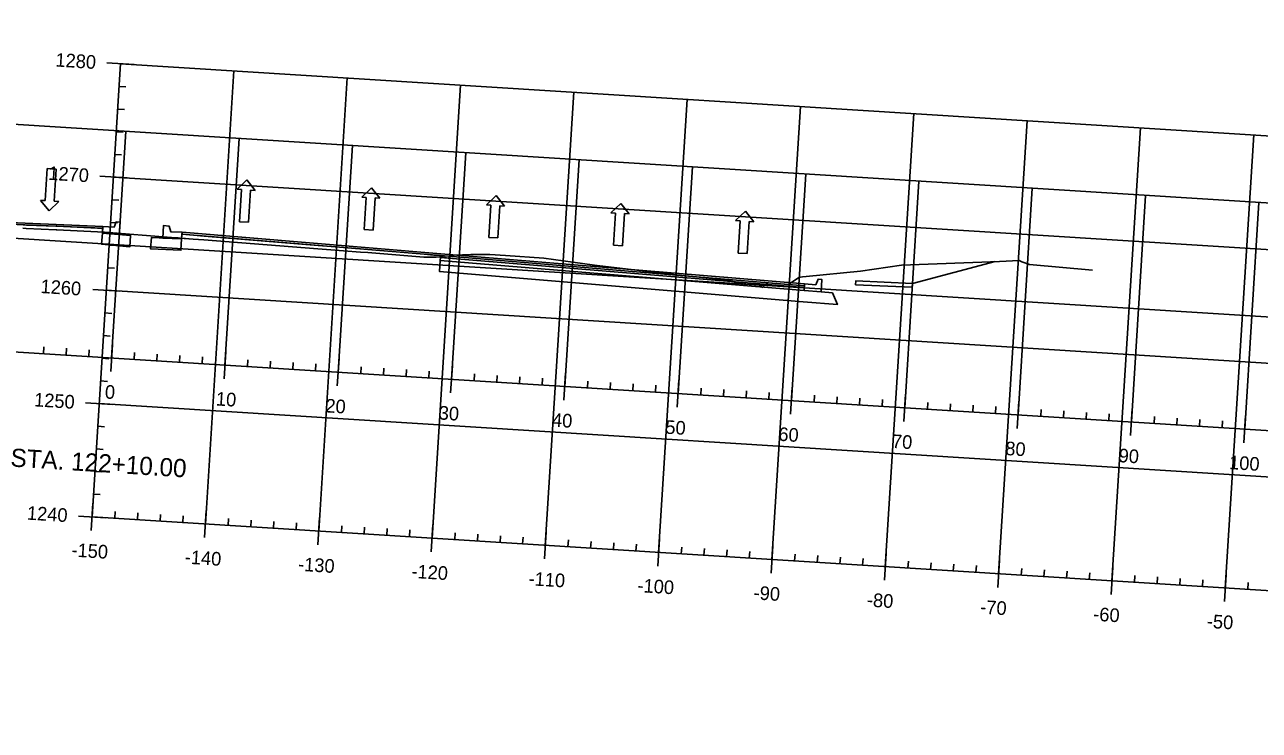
# Model space of a CAD drawing. Extents: x 658976 to 668721, y 639543 to 647196.
# Drawn here: x 660372 to 660916, y 641901 to 642211 of the extents above; entities that cross this region are included whole.
import ezdxf

# ---------------------------------------------------------------- set-up
doc = ezdxf.new("R2010")
doc.units = 0
for name, color, linetype in [('R_Axis', 7, 'Continuous'), ('R_Axis Annot', 7, 'Continuous'), ('R_Exist Surface', 7, 'Continuous'), ('R_Fin Surface', 7, 'Continuous'), ('R_Grid', 7, 'Continuous'), ('R_MOT', 7, 'Continuous'), ('R_Proposed Const Limits', 7, 'Continuous'), ('R_Proposed Road', 7, 'Continuous'), ('R_Sub Surface', 7, 'Continuous')]:
    doc.layers.add(name, color=color, linetype=linetype)

msp = doc.modelspace()

# ---------------------------------------------------------------- linework, layer by layer
for points in [[(660406.87, 642122.59), (660411.85, 642122.18), (660412.84, 642124.62), (660414.5, 642124.52), (660414.16, 642119.06), (660406.69, 642119.68)], [(660441.77, 642120), (660436.78, 642120.21), (660436.1, 642122.76), (660433.61, 642122.92), (660433.26, 642117.44), (660441.59, 642117.09)], [(660715.89, 642097.27), (660720.87, 642096.86), (660721.86, 642099.3), (660723.52, 642099.2), (660723.18, 642093.74), (660715.71, 642094.36)]]:
    msp.add_lwpolyline(points, close=True)
at = {"layer": 'R_Axis'}
for p, q in [((660402.17, 641994.63), (660414.7, 642194.23)), ((660408.72, 642194.61), (660420.69, 642193.86)), ((660414.08, 642184.25), (660417.07, 642184.07)), ((660413.45, 642174.27), (660416.44, 642174.09)), ((660412.82, 642164.29), (660415.82, 642164.11)), ((660412.2, 642154.31), (660415.19, 642154.12)), ((660405.58, 642144.71), (660417.56, 642143.96)), ((660410.94, 642134.35), (660413.94, 642134.16)), ((660410.32, 642124.37), (660413.31, 642124.18)), ((660409.69, 642114.39), (660412.68, 642114.2)), ((659662.22, 642111.64), (661159.27, 642017.62)), ((660409.06, 642104.41), (660412.06, 642104.22)), ((660402.45, 642094.81), (660414.42, 642094.05)), ((660407.81, 642084.45), (660410.8, 642084.26)), ((660407.18, 642074.47), (660410.18, 642074.28)), ((660380.8, 642066.51), (660380.99, 642069.51)), ((660390.78, 642065.89), (660390.97, 642068.88)), ((660410.37, 642058.65), (660411.12, 642070.62)), ((660400.76, 642065.26), (660400.95, 642068.25)), ((660406.56, 642064.49), (660409.55, 642064.3)), ((660420.72, 642064.01), (660420.91, 642067)), ((660430.7, 642063.38), (660430.89, 642066.37)), ((660440.68, 642062.75), (660440.87, 642065.75)), ((660450.66, 642062.13), (660450.85, 642065.12)), ((660460.27, 642055.51), (660461.02, 642067.49)), ((660470.62, 642060.87), (660470.81, 642063.87)), ((660510.17, 642052.38), (660510.92, 642064.35)), ((660480.6, 642060.25), (660480.79, 642063.24)), ((660490.58, 642059.62), (660490.77, 642062.61)), ((660500.57, 642058.99), (660500.75, 642061.99)), ((660520.53, 642057.74), (660520.71, 642060.73)), ((660530.51, 642057.11), (660530.69, 642060.11)), ((660540.49, 642056.49), (660540.67, 642059.48)), ((660550.47, 642055.86), (660550.65, 642058.85)), ((660560.07, 642049.24), (660560.82, 642061.22)), ((660609.97, 642046.11), (660610.72, 642058.09)), ((660405.93, 642054.51), (660408.92, 642054.32)), ((660570.43, 642054.6), (660570.62, 642057.6)), ((660580.41, 642053.98), (660580.6, 642056.97)), ((660590.39, 642053.35), (660590.58, 642056.35)), ((660600.37, 642052.72), (660600.56, 642055.72)), ((660620.33, 642051.47), (660620.52, 642054.46)), ((660630.31, 642050.84), (660630.5, 642053.84)), ((660640.29, 642050.22), (660640.48, 642053.21)), ((660650.27, 642049.59), (660650.46, 642052.58)), ((660659.87, 642042.98), (660660.63, 642054.95)), ((660670.23, 642048.34), (660670.42, 642051.33)), ((660680.21, 642047.71), (660680.4, 642050.7)), ((660690.19, 642047.08), (660690.38, 642050.08)), ((660700.17, 642046.46), (660700.36, 642049.45)), ((660709.78, 642039.84), (660710.53, 642051.82)), ((660720.13, 642045.2), (660720.32, 642048.2)), ((660730.11, 642044.58), (660730.3, 642047.57)), ((660759.68, 642036.71), (660760.43, 642048.68)), ((660399.31, 642044.91), (660411.29, 642044.15)), ((660740.09, 642043.95), (660740.28, 642046.94)), ((660750.07, 642043.32), (660750.26, 642046.32)), ((660770.03, 642042.07), (660770.22, 642045.06)), ((660780.01, 642041.44), (660780.2, 642044.44)), ((660789.99, 642040.81), (660790.18, 642043.81)), ((660799.98, 642040.19), (660800.16, 642043.18)), ((660809.58, 642033.57), (660810.33, 642045.55)), ((660819.94, 642038.93), (660820.12, 642041.93)), ((660859.48, 642030.44), (660860.23, 642042.42)), ((660829.92, 642038.31), (660830.1, 642041.3)), ((660839.9, 642037.68), (660840.08, 642040.67)), ((660849.88, 642037.05), (660850.06, 642040.05)), ((660869.84, 642035.8), (660870.03, 642038.79)), ((660879.82, 642035.17), (660880.01, 642038.17)), ((660889.8, 642034.55), (660889.99, 642037.54)), ((660899.78, 642033.92), (660899.97, 642036.91)), ((660909.38, 642027.3), (660910.14, 642039.28)), ((660404.67, 642034.55), (660407.67, 642034.36)), ((660404.05, 642024.57), (660407.04, 642024.38)), ((660403.42, 642014.59), (660406.42, 642014.4)), ((660402.79, 642004.61), (660405.79, 642004.42)), ((660401.79, 641988.64), (660402.54, 642000.62)), ((660396.18, 641995), (660408.16, 641994.25)), ((660402.17, 641994.63), (661899.22, 641900.61)), ((660412.15, 641994), (660412.34, 641996.99)), ((660422.13, 641993.37), (660422.32, 641996.37)), ((660432.11, 641992.75), (660432.3, 641995.74)), ((660442.09, 641992.12), (660442.28, 641995.11)), ((660451.69, 641985.51), (660452.45, 641997.48)), ((660462.05, 641990.87), (660462.24, 641993.86)), ((660472.03, 641990.24), (660472.22, 641993.23)), ((660501.59, 641982.37), (660502.35, 641994.35)), ((660482.01, 641989.61), (660482.2, 641992.61)), ((660491.99, 641988.99), (660492.18, 641991.98)), ((660511.95, 641987.73), (660512.14, 641990.73)), ((660521.93, 641987.11), (660522.12, 641990.1)), ((660531.91, 641986.48), (660532.1, 641989.47)), ((660541.89, 641985.85), (660542.08, 641988.85)), ((660551.5, 641979.24), (660552.25, 641991.21)), ((660561.85, 641984.6), (660562.04, 641987.59)), ((660601.4, 641976.1), (660602.15, 641988.08)), ((660571.83, 641983.97), (660572.02, 641986.97)), ((660581.81, 641983.34), (660582, 641986.34)), ((660591.79, 641982.72), (660591.98, 641985.71)), ((660611.75, 641981.46), (660611.94, 641984.46)), ((660621.73, 641980.84), (660621.92, 641983.83)), ((660631.72, 641980.21), (660631.9, 641983.2)), ((660641.7, 641979.58), (660641.88, 641982.58)), ((660651.3, 641972.97), (660652.05, 641984.95)), ((660661.66, 641978.33), (660661.84, 641981.32)), ((660671.64, 641977.7), (660671.82, 641980.7)), ((660681.62, 641977.08), (660681.8, 641980.07)), ((660691.6, 641976.45), (660691.79, 641979.44)), ((660701.2, 641969.83), (660701.95, 641981.81)), ((660711.56, 641975.2), (660711.75, 641978.19)), ((660721.54, 641974.57), (660721.73, 641977.56)), ((660731.52, 641973.94), (660731.71, 641976.94)), ((660751.1, 641966.7), (660751.86, 641978.68)), ((660741.5, 641973.32), (660741.69, 641976.31)), ((660761.46, 641972.06), (660761.65, 641975.06)), ((660771.44, 641971.44), (660771.63, 641974.43)), ((660781.42, 641970.81), (660781.61, 641973.8)), ((660791.4, 641970.18), (660791.59, 641973.18)), ((660801, 641963.57), (660801.76, 641975.54)), ((660811.36, 641968.93), (660811.55, 641971.92)), ((660821.34, 641968.3), (660821.53, 641971.3)), ((660850.91, 641960.43), (660851.66, 641972.41)), ((660831.32, 641967.67), (660831.51, 641970.67)), ((660841.3, 641967.05), (660841.49, 641970.04)), ((660861.26, 641965.79), (660861.45, 641968.79)), ((660871.24, 641965.17), (660871.43, 641968.16)), ((660881.22, 641964.54), (660881.41, 641967.53)), ((660891.2, 641963.91), (660891.39, 641966.91)), ((660900.81, 641957.3), (660901.56, 641969.28)), ((660911.16, 641962.66), (660911.35, 641965.65))]:
    msp.add_line(p, q, dxfattribs=at)
at = {"layer": 'R_Exist Surface'}
msp.add_lwpolyline([(660371.72, 642121.74), (660373.17, 642121.68), (660386.3, 642121.08), (660386.58, 642121.06), (660404.5, 642120.24), (660407.7, 642120.06), (660437.16, 642117.77), (660440.01, 642117.54), (660440.8, 642117.47), (660446.68, 642117.01), (660451.38, 642116.66), (660501.65, 642112.7), (660505.39, 642112.41), (660520.36, 642111.31), (660523.65, 642111.04), (660548.26, 642108.99), (660552.68, 642109.05), (660553.75, 642108.99), (660555.12, 642109.19), (660555.63, 642109.24), (660556.31, 642109.12), (660558.99, 642108.61), (660559.48, 642109.07), (660560.29, 642109.81), (660560.77, 642109.85), (660561.58, 642109.9), (660568.96, 642110.18), (660577.3, 642110.24), (660584.24, 642109.83), (660601.17, 642108.57), (660613.82, 642106.78), (660623.46, 642105.57), (660628.29, 642104.86), (660662.06, 642100.89), (660672.56, 642099.87), (660682.37, 642098.82), (660689.4, 642097.2), (660696.11, 642096.73), (660697.44, 642095.69), (660699.62, 642097.68), (660708.9, 642096.96), (660713.38, 642100.09), (660715.09, 642100.31), (660716.57, 642100.49), (660740.5, 642102.84), (660758.65, 642105.49), (660801.74, 642107.2), (660810.43, 642107.55), (660811.68, 642107.02), (660814.97, 642105.84), (660842.77, 642103.28)], dxfattribs=at)
at = {"layer": 'R_Fin Surface'}
msp.add_lwpolyline([(660371.82, 642123.25), (660373.26, 642123.19), (660386.4, 642122.63), (660386.68, 642122.62), (660404.6, 642121.85), (660406.82, 642121.76), (660406.71, 642120.12), (660404.5, 642120.24), (660386.58, 642121.06), (660386.3, 642121.08), (660373.17, 642121.68), (660371.72, 642121.74)], dxfattribs=at)
for points in [[(660441.72, 642119.16), (660446.79, 642118.74), (660451.49, 642118.35), (660501.74, 642114.19), (660505.48, 642113.88), (660520.44, 642112.64), (660523.74, 642112.37), (660548.35, 642110.32), (660552.73, 642109.96), (660553.81, 642109.87), (660555.16, 642109.76), (660555.66, 642109.72), (660555.63, 642109.24), (660555.12, 642109.19), (660553.75, 642108.99), (660552.68, 642109.05), (660548.26, 642108.99), (660523.65, 642111.04), (660520.36, 642111.31), (660505.39, 642112.41), (660501.65, 642112.7), (660451.38, 642116.66), (660446.68, 642117.01), (660441.61, 642117.41)], [(660441.59, 642117.09), (660441.28, 642112.1), (660427.95, 642112.66), (660428.27, 642117.65)], [(660555.61, 642108.89), (660715.79, 642095.61), (660715.71, 642094.36), (660555.53, 642107.64)], [(660555.66, 642109.72), (660715.84, 642096.44), (660715.79, 642095.61), (660555.61, 642108.89)]]:
    msp.add_lwpolyline(points, close=True, dxfattribs=at)
at = {"layer": 'R_Grid'}
for p, q in [((659668.48, 642211.45), (661165.54, 642117.43)), ((660402.17, 641994.63), (660414.7, 642194.23)), ((660414.7, 642194.23), (661911.75, 642100.21)), ((660452.07, 641991.49), (660464.61, 642191.1)), ((660501.97, 641988.36), (660514.51, 642187.97)), ((660551.87, 641985.23), (660564.41, 642184.83)), ((660601.77, 641982.09), (660614.31, 642181.7)), ((660651.68, 641978.96), (660664.21, 642178.56)), ((660701.58, 641975.82), (660714.11, 642175.43)), ((660751.48, 641972.69), (660764.02, 642172.3)), ((660801.38, 641969.56), (660813.92, 642169.16)), ((659665.35, 642161.55), (661162.4, 642067.52)), ((660410.74, 642064.63), (660417.01, 642164.44)), ((660460.64, 642061.5), (660466.91, 642161.3)), ((660851.28, 641966.42), (660863.82, 642166.03)), ((660901.18, 641963.29), (660913.72, 642162.89)), ((660510.55, 642058.37), (660516.81, 642158.17)), ((660560.45, 642055.23), (660566.72, 642155.03)), ((660610.35, 642052.1), (660616.62, 642151.9)), ((660660.25, 642048.96), (660666.52, 642148.77)), ((660710.15, 642045.83), (660716.42, 642145.63)), ((660411.57, 642144.33), (661908.62, 642050.31)), ((660760.05, 642042.7), (660766.32, 642142.5)), ((660809.96, 642039.56), (660816.22, 642139.36)), ((660859.86, 642036.43), (660866.13, 642136.23)), ((660909.76, 642033.29), (660916.03, 642133.1)), ((659662.22, 642111.64), (661159.27, 642017.62)), ((660408.44, 642094.43), (661905.49, 642000.41)), ((660405.3, 642044.53), (661902.35, 641950.51)), ((660402.17, 641994.63), (661899.22, 641900.61))]:
    msp.add_line(p, q, dxfattribs=at)
at = {"layer": 'R_MOT'}
for p, q in [((660382.37, 642148.11), (660381.48, 642133.94)), ((660386.36, 642147.86), (660382.37, 642148.11)), ((660385.47, 642133.69), (660386.36, 642147.86)), ((660470.28, 642143.09), (660466.02, 642138.96)), ((660474, 642138.46), (660470.28, 642143.09)), ((660525.17, 642139.64), (660520.91, 642135.51)), ((660528.89, 642135.01), (660525.17, 642139.64)), ((660466.02, 642138.96), (660468.01, 642138.83)), ((660468.01, 642138.83), (660467.12, 642124.66)), ((660471.11, 642124.41), (660472, 642138.58)), ((660472, 642138.58), (660474, 642138.46)), ((660520.91, 642135.51), (660522.9, 642135.39)), ((660522.9, 642135.39), (660522.01, 642121.21)), ((660526.01, 642120.96), (660526.9, 642135.14)), ((660526.9, 642135.14), (660528.89, 642135.01)), ((660580.07, 642136.19), (660575.8, 642132.06)), ((660583.78, 642131.56), (660580.07, 642136.19)), ((660381.48, 642133.94), (660379.48, 642134.06)), ((660379.48, 642134.06), (660383.2, 642129.44)), ((660383.2, 642129.44), (660387.47, 642133.56)), ((660387.47, 642133.56), (660385.47, 642133.69)), ((660575.8, 642132.06), (660577.8, 642131.94)), ((660577.8, 642131.94), (660576.91, 642117.76)), ((660580.9, 642117.51), (660581.79, 642131.69)), ((660581.79, 642131.69), (660583.78, 642131.56)), ((660634.96, 642132.74), (660630.69, 642128.62)), ((660638.68, 642128.12), (660634.96, 642132.74)), ((660689.85, 642129.3), (660685.58, 642125.17)), ((660693.57, 642124.67), (660689.85, 642129.3)), ((660467.12, 642124.66), (660471.11, 642124.41)), ((660630.69, 642128.62), (660632.69, 642128.49)), ((660632.69, 642128.49), (660631.8, 642114.32)), ((660635.79, 642114.06), (660636.68, 642128.24)), ((660636.68, 642128.24), (660638.68, 642128.12)), ((660685.58, 642125.17), (660687.58, 642125.04)), ((660687.58, 642125.04), (660686.69, 642110.87)), ((660690.68, 642110.62), (660691.57, 642124.79)), ((660691.57, 642124.79), (660693.57, 642124.67)), ((660522.01, 642121.21), (660526.01, 642120.96)), ((660576.91, 642117.76), (660580.9, 642117.51)), ((660631.8, 642114.32), (660635.79, 642114.06)), ((660686.69, 642110.87), (660690.68, 642110.62))]:
    msp.add_line(p, q, dxfattribs=at)
at = {"layer": 'R_Proposed Const Limits'}
for points in [[(660241.98, 642129.64), (660241.93, 642128.81), (660276.7, 642127.32), (660406.82, 642121.76), (660406.87, 642122.59), (660276.75, 642128.15)], [(660715.84, 642096.44), (660715.89, 642097.27), (660555.72, 642110.55), (660441.77, 642120), (660441.72, 642119.16), (660555.66, 642109.72)]]:
    msp.add_lwpolyline(points, close=True, dxfattribs=at)
msp.add_lwpolyline([(660763.5, 642097.49), (660763.5, 642097.49), (660799.9, 642107.13)], dxfattribs=at)
at = {"layer": 'R_Proposed Road'}
msp.add_lwpolyline([(660763.5, 642097.49), (660738.51, 642098.56), (660738.41, 642096.89), (660763.39, 642095.83)], close=True, dxfattribs=at)
at = {"layer": 'R_Sub Surface'}
for points in [[(660406.69, 642119.68), (660406.37, 642114.69), (660418.83, 642113.66), (660419.15, 642118.65)], [(660555.53, 642107.64), (660715.71, 642094.36), (660723.18, 642093.74), (660728.17, 642093.33), (660730.37, 642088.13), (660715.39, 642089.37), (660555.22, 642102.65)]]:
    msp.add_lwpolyline(points, close=True, dxfattribs=at)

# ---------------------------------------------------------------- texts
at = {"layer": 'R_Axis Annot'}
for s, height, p in [('1280', 6, (660385.9, 642193.04)), ('1270', 6, (660382.77, 642143.14)), ('1260', 6, (660379.35, 642093.25)), ('0', 6, (660407.66, 642046.79)), ('1250', 6, (660376.5, 642043.33)), ('10', 6, (660456.57, 642043.72)), ('20', 6, (660504.77, 642040.69)), ('30', 6, (660554.68, 642037.56)), ('40', 6, (660604.58, 642034.42)), ('50', 6, (660654.48, 642031.29)), ('60', 6, (660704.24, 642028.17)), ('70', 6, (660754.28, 642025.02)), ('80', 6, (660804.18, 642021.89)), ('STA. 122+10.00', 8, (660366.06, 642016.84)), ('90', 6, (660854.09, 642018.75)), ('100', 6, (660902.76, 642015.7)), ('1240', 6, (660373.37, 641993.43)), ('-150', 6, (660392.96, 641977.17)), ('-140', 6, (660442.86, 641974.04)), ('-130', 6, (660492.76, 641970.9)), ('-120', 6, (660542.66, 641967.77)), ('-110', 6, (660594.26, 641964.53)), ('-100', 6, (660642.23, 641961.52)), ('-90', 6, (660693.36, 641958.3)), ('-80', 6, (660743.26, 641955.17)), ('-70', 6, (660793.16, 641952.04)), ('-60', 6, (660842.92, 641948.91)), ('-50', 6, (660892.96, 641945.77))]:
    msp.add_text(s, height=height, rotation=356.4063, dxfattribs=at).set_placement(p)

doc.saveas('drawing.dxf')
